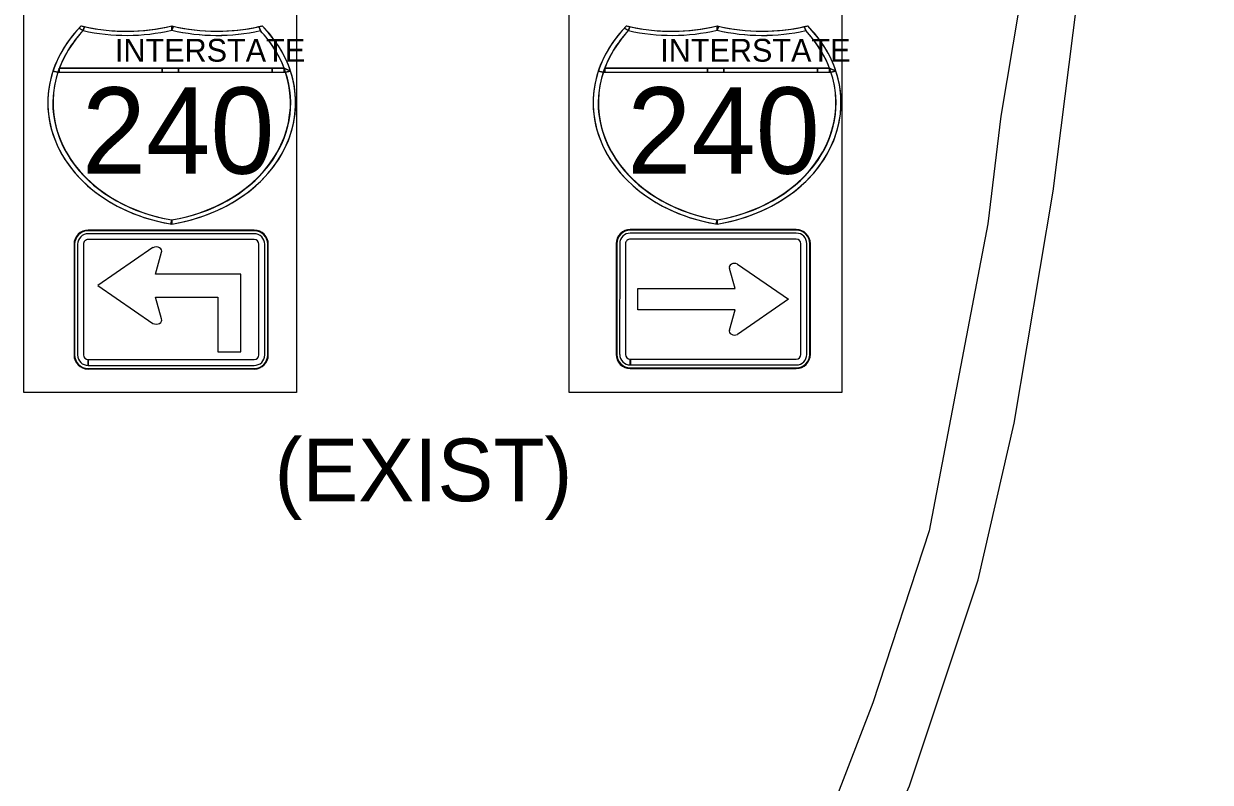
# Model space of a CAD drawing. Extents: x 886234 to 968767, y 455416 to 684046.
# Drawn here: x 914040 to 916171, y 500004 to 501367 of the extents above; entities that cross this region are included whole.
import ezdxf

# ---------------------------------------------------------------- set-up
doc = ezdxf.new("R2010")
doc.units = 0
for name, color, linetype in [('TC DEV SIGN BLACK 239', 7, 'Continuous'), ('TC DEV SIGN BLACK ZERO', 7, 'Continuous'), ('TC DEV SIGN WHITE', 7, 'Continuous'), ('TC LABEL TEXT', 7, 'Continuous')]:
    doc.layers.add(name, color=color, linetype=linetype)

msp = doc.modelspace()

# ---------------------------------------------------------------- linework, layer by layer
at = {"layer": 'TC DEV SIGN BLACK 239'}
for p, q in [((914453.5, 500990), (914155.3, 500990)), ((914453.5, 500979.5), (914155.3, 500979.5)), ((915427.1, 500991), (915129, 500991)), ((915427.1, 500980.4), (915129, 500980.4)), ((914136.3, 500971), (914136.3, 500772.2)), ((914146.9, 500971), (914146.9, 500772.2)), ((914271.7, 500964.9), (914172.9, 500896.8)), ((914276, 500917.1), (914287.1, 500956.6)), ((914461.9, 500772.2), (914461.9, 500971)), ((914472.5, 500772.2), (914472.5, 500971)), ((915110, 500972), (915109.9, 500773.2)), ((915120.5, 500972), (915120.5, 500773.2)), ((915435.6, 500773.2), (915435.6, 500972)), ((915446.1, 500773.2), (915446.1, 500972)), ((915321.6, 500935.3), (915413.2, 500872.2)), ((914429.6, 500917.1), (914276, 500917.1)), ((914429.6, 500778), (914429.6, 500917.1)), ((915317.6, 500891.6), (915307.3, 500927.6)), ((914172.9, 500896.8), (914271.7, 500828.8)), ((915142.7, 500853.4), (915142.7, 500891.6)), ((915142.7, 500891.6), (915317.6, 500891.6)), ((914287.1, 500837.1), (914276, 500875.8)), ((914276, 500875.8), (914388.3, 500875.8)), ((914388.3, 500875.8), (914388.3, 500778)), ((915413.2, 500872.2), (915321.6, 500809.1)), ((915317.6, 500853.4), (915142.7, 500853.4)), ((915307.3, 500816.7), (915317.6, 500853.4)), ((914155.3, 500753.2), (914155.3, 500763.8)), ((914155.4, 500763.8), (914453.5, 500763.8)), ((914155.4, 500763.8), (914155.4, 500753.2)), ((914388.3, 500778), (914429.6, 500778)), ((915129, 500754.2), (915129, 500764.7)), ((915129.1, 500764.7), (915427.1, 500764.7)), ((915129.1, 500764.7), (915129.1, 500754.2)), ((914155.4, 500753.2), (914453.5, 500753.2)), ((915129.1, 500754.2), (915427.1, 500754.2))]:
    msp.add_line(p, q, dxfattribs=at)
for centre, major_axis, ratio, start_param, end_param in [((914155.3, 500971), (19, 0), 0.999865, 1.570796, 3.141593), ((914155.3, 500971), (8.45, 0), 0.999865, 1.570796, 3.141593), ((914453.5, 500971), (19, 0), 0.999865, 0, 1.570796), ((914453.5, 500971), (8.45, 0), 0.999865, 0, 1.570796), ((915129, 500972), (19, 0), 0.999865, 1.570796, 3.141593), ((915129, 500972), (8.45, 0), 0.999865, 1.570796, 3.141593), ((915427.1, 500972), (19, 0), 0.999865, 0, 1.570796), ((915427.1, 500972), (8.45, 0), 0.999865, 0, 1.570796), ((914277.5, 500958.8), (-10.2, 0), 0.720018, 2.830617, 5.313577), ((915316.2, 500929.7), (9.44, 0), 0.720018, 0.96961, 3.452569), ((914277.5, 500834.8), (-10.2, 0), 0.720018, 0.96961, 3.452569), ((915316.2, 500814.7), (9.44, 0), 0.720018, 2.830617, 5.313577), ((914155.3, 500772.2), (19, 0), 0.999865, 3.141593, 4.712389), ((914155.3, 500772.2), (8.45, 0), 0.999865, 3.141593, 4.712389), ((914453.5, 500772.2), (19, 0), 0.999865, 4.712389, 6.283185), ((914453.5, 500772.2), (8.45, 0), 0.999865, 4.712389, 6.283185), ((915129, 500773.2), (19, 0), 0.999865, 3.141593, 4.712389), ((915129, 500773.2), (8.45, 0), 0.999865, 3.141593, 4.712389), ((915427.1, 500773.2), (19, 0), 0.999865, 4.712389, 6.283185), ((915427.1, 500773.2), (8.45, 0), 0.999865, 4.712389, 6.283185)]:
    msp.add_ellipse(centre, major_axis=major_axis, ratio=ratio, start_param=start_param, end_param=end_param, dxfattribs=at)
at = {"layer": 'TC DEV SIGN BLACK ZERO'}
for p, q in [((914146.2, 501354.9), (914148.7, 501362)), ((914305.7, 501355.7), (914305.4, 501363.4)), ((914305.6, 501356.2), (914305.4, 501363.4)), ((914462.1, 501362), (914464.6, 501354.9)), ((915125.7, 501354.9), (915128.2, 501362)), ((915285.2, 501355.7), (915284.9, 501363.4)), ((915285.1, 501356.2), (915284.9, 501363.4)), ((915441.6, 501362), (915444.1, 501354.9)), ((914100.9, 501280), (914510, 501280)), ((914100.9, 501280), (914103.5, 501280)), ((914103.5, 501287.4), (914507.3, 501287.4)), ((914288.4, 501287.4), (914103.5, 501287.4)), ((914103.5, 501280), (914288.4, 501280)), ((914317.7, 501287.4), (914288.4, 501287.4)), ((914288.4, 501280), (914317.7, 501280)), ((914485.5, 501287.4), (914317.7, 501287.4)), ((914317.7, 501280), (914485.5, 501280)), ((914507.3, 501287.4), (914485.5, 501287.4)), ((914485.5, 501280), (914507.3, 501280)), ((914518.9, 501281.9), (914507.3, 501287.4)), ((914509.8, 501280.5), (914507.3, 501280)), ((914507.3, 501280), (914510, 501280)), ((915080.4, 501280), (915489.5, 501280)), ((915080.4, 501280), (915083, 501280)), ((915083, 501287.4), (915486.9, 501287.4)), ((915267.9, 501287.4), (915083, 501287.4)), ((915083, 501280), (915267.9, 501280)), ((915297.2, 501287.4), (915267.9, 501287.4)), ((915267.9, 501280), (915297.2, 501280)), ((915465, 501287.4), (915297.2, 501287.4)), ((915297.2, 501280), (915465, 501280)), ((915486.9, 501287.4), (915465, 501287.4)), ((915465, 501280), (915486.9, 501280)), ((915498.4, 501281.9), (915486.9, 501287.4)), ((915489.3, 501280.5), (915486.9, 501280)), ((915486.9, 501280), (915489.5, 501280)), ((914082.8, 501226.4), (914082.8, 501224.2)), ((914528.1, 501224.2), (914528.1, 501226.5)), ((915062.3, 501226.4), (915062.3, 501224.2)), ((915507.6, 501224.2), (915507.6, 501226.5)), ((914453.5, 500996.4), (914155.3, 500996.4)), ((914155.3, 500995.3), (914155.3, 500995.3)), ((914453.5, 500995.3), (914155.3, 500995.3)), ((914305.4, 501007.2), (914305.4, 501014.7)), ((914453.5, 500995.3), (914453.5, 500995.3)), ((915427.1, 500997.3), (915129, 500997.3)), ((915129, 500996.3), (915129, 500996.3)), ((915427.1, 500996.3), (915129, 500996.3)), ((915284.9, 501007.2), (915284.9, 501014.7)), ((915427.1, 500996.3), (915427.1, 500996.3)), ((914130, 500971), (914130, 500772.2)), ((914131, 500971), (914131, 500772.2)), ((914131, 500971), (914131, 500971)), ((914477.8, 500971), (914477.8, 500971)), ((914477.8, 500772.2), (914477.8, 500971)), ((914478.8, 500772.2), (914478.8, 500971)), ((915103.6, 500972), (915103.6, 500773.2)), ((915104.7, 500972), (915104.7, 500773.2)), ((915104.7, 500972), (915104.7, 500972)), ((915451.4, 500972), (915451.4, 500972)), ((915451.4, 500773.2), (915451.4, 500972)), ((915452.5, 500773.2), (915452.5, 500972)), ((914131, 500772.2), (914131, 500772.2)), ((914477.8, 500772.2), (914477.8, 500772.2)), ((915104.7, 500773.2), (915104.7, 500773.2)), ((915451.4, 500773.2), (915451.4, 500773.2)), ((914155.3, 500746.9), (914155.3, 500747.9)), ((914155.3, 500747.9), (914155.3, 500747.9)), ((914155.3, 500747.9), (914453.5, 500747.9)), ((914155.3, 500747.9), (914155.3, 500746.9)), ((914155.3, 500746.9), (914453.5, 500746.9)), ((914453.5, 500747.9), (914453.5, 500747.9)), ((915129, 500747.8), (915129, 500748.9)), ((915129, 500748.9), (915129, 500748.9)), ((915129, 500748.9), (915427.1, 500748.9)), ((915129, 500748.9), (915129, 500747.8)), ((915129, 500747.8), (915427.1, 500747.8)), ((915427.1, 500748.9), (915427.1, 500748.9))]:
    msp.add_line(p, q, dxfattribs=at)
for points in [[(914138.8, 501359.3), (914146.2, 501354.9)], [(914146.2, 501354.9), (914138.8, 501359.3)], [(914142.8, 501363.4), (914142.7, 501363.4), (914142.7, 501363.4)], [(914148.7, 501362), (914146.2, 501354.9)], [(914305.6, 501363.4), (914305.6, 501356.2), (914308.3, 501362.7)], [(914308.3, 501362.7), (914305.7, 501355.7)], [(914464.6, 501354.9), (914462.1, 501362)], [(914468.1, 501363.4), (914468.1, 501363.4), (914468.1, 501363.4)], [(915118.3, 501359.3), (915125.7, 501354.9)], [(915125.7, 501354.9), (915118.3, 501359.3)], [(915122.3, 501363.4), (915122.3, 501363.4), (915122.3, 501363.4)], [(915128.2, 501362), (915125.7, 501354.9)], [(915285.1, 501363.4), (915285.1, 501356.2), (915287.8, 501362.7)], [(915287.8, 501362.7), (915285.2, 501355.7)], [(915444.1, 501354.9), (915441.6, 501362)], [(915447.6, 501363.4), (915447.6, 501363.4), (915447.6, 501363.4)], [(914305.4, 501355.7), (914305.6, 501356.2)], [(915284.9, 501355.7), (915285.1, 501356.2)], [(914091.9, 501281.9), (914100.9, 501280)], [(914100.9, 501280), (914091.9, 501281.9)], [(914103.5, 501287.4), (914103.5, 501280)], [(914103.5, 501280), (914103.5, 501287.4)], [(914288.4, 501280), (914288.4, 501287.4)], [(914288.4, 501287.4), (914288.4, 501280)], [(914317.7, 501287.4), (914317.7, 501280)], [(914317.7, 501280), (914317.7, 501287.4)], [(914485.5, 501280), (914485.5, 501287.4)], [(914485.5, 501287.4), (914485.5, 501280)], [(914507.3, 501287.4), (914518.9, 501281.9)], [(914507.3, 501280), (914507.3, 501287.4)], [(914507.3, 501287.4), (914507.3, 501280), (914509.8, 501280.5), (914507.3, 501287.4)], [(914510, 501280), (914509.8, 501280.5)], [(914518.9, 501281.9), (914510, 501280)], [(914510, 501280), (914518.9, 501281.9)], [(915071.4, 501281.9), (915080.4, 501280)], [(915080.4, 501280), (915071.4, 501281.9)], [(915083, 501287.4), (915083, 501280)], [(915083, 501280), (915083, 501287.4)], [(915267.9, 501280), (915267.9, 501287.4)], [(915267.9, 501287.4), (915267.9, 501280)], [(915297.2, 501287.4), (915297.2, 501280)], [(915297.2, 501280), (915297.2, 501287.4)], [(915465, 501280), (915465, 501287.4)], [(915465, 501287.4), (915465, 501280)], [(915486.9, 501287.4), (915498.4, 501281.9)], [(915486.9, 501280), (915486.9, 501287.4)], [(915486.9, 501287.4), (915486.9, 501280), (915489.3, 501280.5), (915486.9, 501287.4)], [(915489.5, 501280), (915489.3, 501280.5)], [(915498.4, 501281.9), (915489.5, 501280)], [(915489.5, 501280), (915498.4, 501281.9)], [(914303.5, 501007.5), (914305.4, 501014.7)], [(914305.4, 501014.7), (914303.5, 501007.5), (914305.4, 501007.2)], [(914305.4, 501014.7), (914305.4, 501007.2)], [(915283, 501007.5), (915284.9, 501014.7)], [(915284.9, 501014.7), (915283, 501007.5), (915284.9, 501007.2)], [(915284.9, 501014.7), (915284.9, 501007.2)]]:
    msp.add_lwpolyline(points, dxfattribs=at)
for centre, major_axis, ratio, start_param, end_param in [((914361.1, 501225.3), (-278.3, 0), 0.800002, 5.614188, 7.652625), ((914361.1, 501225.3), (-278.3, 0), 0.800002, 5.637358, 6.026219), ((914361.1, 501225.3), (-278.3, 0), 0.800002, 5.614216, 5.637358), ((914224.1, 501576.4), (278.3, 0), 0.800002, 4.415792, 5.008922), ((914224.1, 501576.4), (278.3, 0), 0.800002, 4.415856, 4.438209), ((914224.1, 501576.4), (278.3, 0), 0.800002, 4.438209, 5.008909), ((914386.7, 501576.4), (278.3, 0), 0.800002, 4.415856, 5.008986), ((914249.7, 501225.3), (278.3, 0), 0.800002, 4.913746, 6.952183), ((914386.7, 501576.4), (278.3, 0), 0.800002, 4.416709, 4.426515), ((914386.7, 501576.4), (278.3, 0), 0.800002, 4.426515, 4.986569), ((914386.7, 501576.4), (278.3, 0), 0.800002, 4.986569, 5.008922), ((914249.7, 501225.3), (278.3, 0), 0.800002, 0.256966, 0.66897), ((915340.6, 501225.3), (-278.3, 0), 0.800002, 5.614188, 7.652625), ((915340.6, 501225.3), (-278.3, 0), 0.800002, 5.637358, 6.026219), ((915340.6, 501225.3), (-278.3, 0), 0.800002, 5.614216, 5.637358), ((915203.6, 501576.4), (278.3, 0), 0.800002, 4.415792, 5.008922), ((915203.6, 501576.4), (278.3, 0), 0.800002, 4.415856, 4.438209), ((915203.6, 501576.4), (278.3, 0), 0.800002, 4.438209, 5.008909), ((915366.2, 501576.4), (278.3, 0), 0.800002, 4.415856, 5.008986), ((915229.3, 501225.3), (278.3, 0), 0.800002, 4.913746, 6.952183), ((915366.2, 501576.4), (278.3, 0), 0.800002, 4.416709, 4.426515), ((915366.2, 501576.4), (278.3, 0), 0.800002, 4.426515, 4.986569), ((915366.2, 501576.4), (278.3, 0), 0.800002, 4.986569, 5.008922), ((915229.3, 501225.3), (278.3, 0), 0.800002, 0.256966, 0.66897), ((914361.1, 501225.3), (-269, 0), 0.800002, 5.637358, 7.64558), ((914361.1, 501225.3), (-269, 0), 0.800002, 5.637358, 6.026219), ((914224.1, 501576.4), (287.6, 0), 0.800002, 4.438209, 4.999074), ((914224.1, 501576.4), (287.6, 0), 0.800002, 4.438209, 4.999074), ((914386.7, 501576.4), (287.6, 0), 0.800002, 4.425704, 4.986569), ((914249.7, 501225.3), (269, 0), 0.800002, 4.920791, 6.929013), ((914386.9, 501576), (287.2, 0), 0.800002, 4.425686, 4.986568), ((914249.7, 501225.3), (269, 0), 0.800002, 0.292795, 0.645828), ((915340.6, 501225.3), (-269, 0), 0.800002, 5.637358, 7.64558), ((915340.6, 501225.3), (-269, 0), 0.800002, 5.637358, 6.026219), ((915203.6, 501576.4), (287.6, 0), 0.800002, 4.438209, 4.999074), ((915203.6, 501576.4), (287.6, 0), 0.800002, 4.438209, 4.999074), ((915366.2, 501576.4), (287.6, 0), 0.800002, 4.425704, 4.986569), ((915229.3, 501225.3), (269, 0), 0.800002, 4.920791, 6.929013), ((915366.4, 501576), (287.2, 0), 0.800002, 4.425686, 4.986568), ((915229.3, 501225.3), (269, 0), 0.800002, 0.292795, 0.645828), ((914359.8, 501224.7), (-268, 0), 0.800002, 6.022151, 7.649781), ((914361.1, 501225.3), (-278.3, 0), 0.800002, 6.026219, 6.278259), ((914361.1, 501225.3), (-269, 0), 0.800002, 5.99039, 6.026219), ((914251.1, 501224.7), (268, 0), 0.800002, 4.916934, 6.544356), ((914249.7, 501225.3), (269, 0), 0.800002, 0.256966, 0.292795), ((914249.7, 501225.3), (278.3, 0), 0.800002, 0.005231, 0.256966), ((915339.3, 501224.7), (-268, 0), 0.800002, 6.022151, 7.649781), ((915340.6, 501225.3), (-278.3, 0), 0.800002, 6.026219, 6.278259), ((915340.6, 501225.3), (-269, 0), 0.800002, 5.99039, 6.026219), ((915230.6, 501224.7), (268, 0), 0.800002, 4.916934, 6.544356), ((915229.3, 501225.3), (269, 0), 0.800002, 0.256966, 0.292795), ((915229.3, 501225.3), (278.3, 0), 0.800002, 0.005231, 0.256966), ((914361.1, 501225.3), (-278.3, 0), 0.800002, 0.004927, 1.362388), ((914249.7, 501225.3), (278.3, 0), 0.800002, 4.913748, 6.277955), ((915340.6, 501225.3), (-278.3, 0), 0.800002, 0.004927, 1.362388), ((915229.3, 501225.3), (278.3, 0), 0.800002, 4.913748, 6.277955), ((914155.3, 500971), (25.4, 0), 0.999865, 1.570796, 3.141593), ((914155.3, 500971), (24.3, 0), 0.999865, 1.570796, 3.141593), ((914249.7, 501225.3), (269, 0), 0.800002, 4.920791, 4.921138), ((914361.1, 501225.3), (-278.3, 0), 0.800002, 1.36935, 1.369438), ((914249.7, 501225.3), (278.3, 0), 0.800002, 4.913747, 4.913748), ((914453.5, 500971), (25.4, 0), 0.999865, 0, 1.570796), ((914453.5, 500971), (24.3, 0), 0.999865, 0, 1.570796), ((915129, 500972), (25.4, 0), 0.999865, 1.570796, 3.141593), ((915129, 500972), (24.3, 0), 0.999865, 1.570796, 3.141593), ((915229.3, 501225.3), (269, 0), 0.800002, 4.920791, 4.921138), ((915340.6, 501225.3), (-278.3, 0), 0.800002, 1.36935, 1.369438), ((915229.3, 501225.3), (278.3, 0), 0.800002, 4.913747, 4.913748), ((915427.1, 500972), (25.4, 0), 0.999865, 0, 1.570796), ((915427.1, 500972), (24.3, 0), 0.999865, 0, 1.570796), ((914155.3, 500772.2), (25.4, 0), 0.999865, 3.141593, 4.712389), ((914155.3, 500772.2), (24.3, 0), 0.999865, 3.141593, 4.712389), ((914453.5, 500772.2), (25.4, 0), 0.999865, 4.712389, 6.283185), ((914453.5, 500772.2), (24.3, 0), 0.999865, 4.712389, 6.283185), ((915129, 500773.2), (25.4, 0), 0.999865, 3.141593, 4.712389), ((915129, 500773.2), (24.3, 0), 0.999865, 3.141593, 4.712389), ((915427.1, 500773.2), (25.4, 0), 0.999865, 4.712389, 6.283185), ((915427.1, 500773.2), (24.3, 0), 0.999865, 4.712389, 6.283185)]:
    msp.add_ellipse(centre, major_axis=major_axis, ratio=ratio, start_param=start_param, end_param=end_param, dxfattribs=at)
at = {"layer": 'TC DEV SIGN WHITE'}
for p, q in [((914453.5, 500996.4), (914155.3, 500996.4)), ((915427.1, 500997.3), (915129, 500997.3)), ((914130, 500971), (914130, 500772.2)), ((914478.8, 500772.2), (914478.8, 500971)), ((915103.6, 500972), (915103.6, 500773.2)), ((915452.5, 500773.2), (915452.5, 500972)), ((914155.3, 500746.9), (914453.5, 500746.9)), ((915129, 500747.8), (915427.1, 500747.8))]:
    msp.add_line(p, q, dxfattribs=at)
for centre, start_param, end_param in [((914155.3, 500971), 1.570796, 3.141593), ((914453.5, 500971), 0, 1.570796), ((915129, 500972), 1.570796, 3.141593), ((915427.1, 500972), 0, 1.570796), ((914155.3, 500772.2), 3.141593, 4.712389), ((914453.5, 500772.2), 4.712389, 6.283185), ((915129, 500773.2), 3.141593, 4.712389), ((915427.1, 500773.2), 4.712389, 6.283185)]:
    msp.add_ellipse(centre, major_axis=(25.4, 0), ratio=0.999865, start_param=start_param, end_param=end_param, dxfattribs=at)
at = {"layer": 'TC LABEL TEXT'}
for points in [[(916068.7, 503296), (916043.5, 503081.2), (915918.4, 502163.8), (915847.6, 501518.3), (915794.8, 501201.3), (915771.4, 501007.6), (915665.8, 500455.8), (915564.8, 500147), (915378.3, 499663.4)], [(914514.9, 497965.9), (914613.1, 498228.3), (914701.8, 498403.8), (914803.7, 498581.2), (914913.1, 498751), (915202.3, 499146.9), (915425.3, 499534.3), (915630.6, 499998), (915753.8, 500367.8), (915818.3, 500649.5), (915888.7, 501066.3), (916133.3, 503006.5), (916170.7, 503246.7)]]:
    msp.add_lwpolyline(points, dxfattribs=at)
for points in [[(914039.6, 501615.6), (914529.3, 501615.6), (914529.3, 500704.7), (914039.6, 500704.7)], [(915019.1, 501615.6), (915508.8, 501615.6), (915508.8, 500704.7), (915019.1, 500704.7)]]:
    msp.add_lwpolyline(points, close=True, dxfattribs=at)

# ---------------------------------------------------------------- texts
at = {"layer": 'TC DEV SIGN BLACK ZERO'}
for s, height, p in [('INTERSTATE', 41.06, (914203.4, 501299)), ('INTERSTATE', 41.06, (915182.9, 501299)), ('240', 155.13, (914143.9, 501097.8)), ('240', 155.13, (915123.4, 501097.8))]:
    msp.add_text(s, height=height, rotation=360, dxfattribs=at).set_placement(p)
at = {"layer": 'TC LABEL TEXT'}
msp.add_text('(EXIST)', height=112.5, dxfattribs=at).set_placement((914490.1, 500509.3))

doc.saveas('drawing.dxf')
